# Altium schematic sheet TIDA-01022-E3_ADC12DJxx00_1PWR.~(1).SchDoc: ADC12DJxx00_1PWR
size 431 x 279 mm; Date: Not shown in title block; ApprovedBy: Not shown in title block; CheckedBy: Not shown in title block; Author: Not shown in title block; CompanyName: Not shown in title block; DrawnBy: Avinash N; Engineer: Not shown in title block; Organization: Not shown in title block; Address1: Not shown in title block; Address2: Not shown in title block; Address3: Not shown in title block; Address4: Not shown in title block; DocumentNumber: 1; Revision: Use project parameter SCH_Rev; SheetNumber: 7; SheetTotal: 26; PageSetup: Record=PageOptions¦CenterHorizontal=True¦CenterVertical=True¦PrintScale=1.00¦XCorrection=1.00¦YCorrection=1.00¦PrintKind=0¦BorderSize=5000000¦LeftOffset=0¦BottomOffset=0¦Orientation=2¦PaperLength=1000¦PaperWidth=1000¦Scale=100¦PaperSource=15¦PrintQuality=600¦MediaType=1¦DitherType=10¦PaperKind=Letter¦PrintScaleMode=1
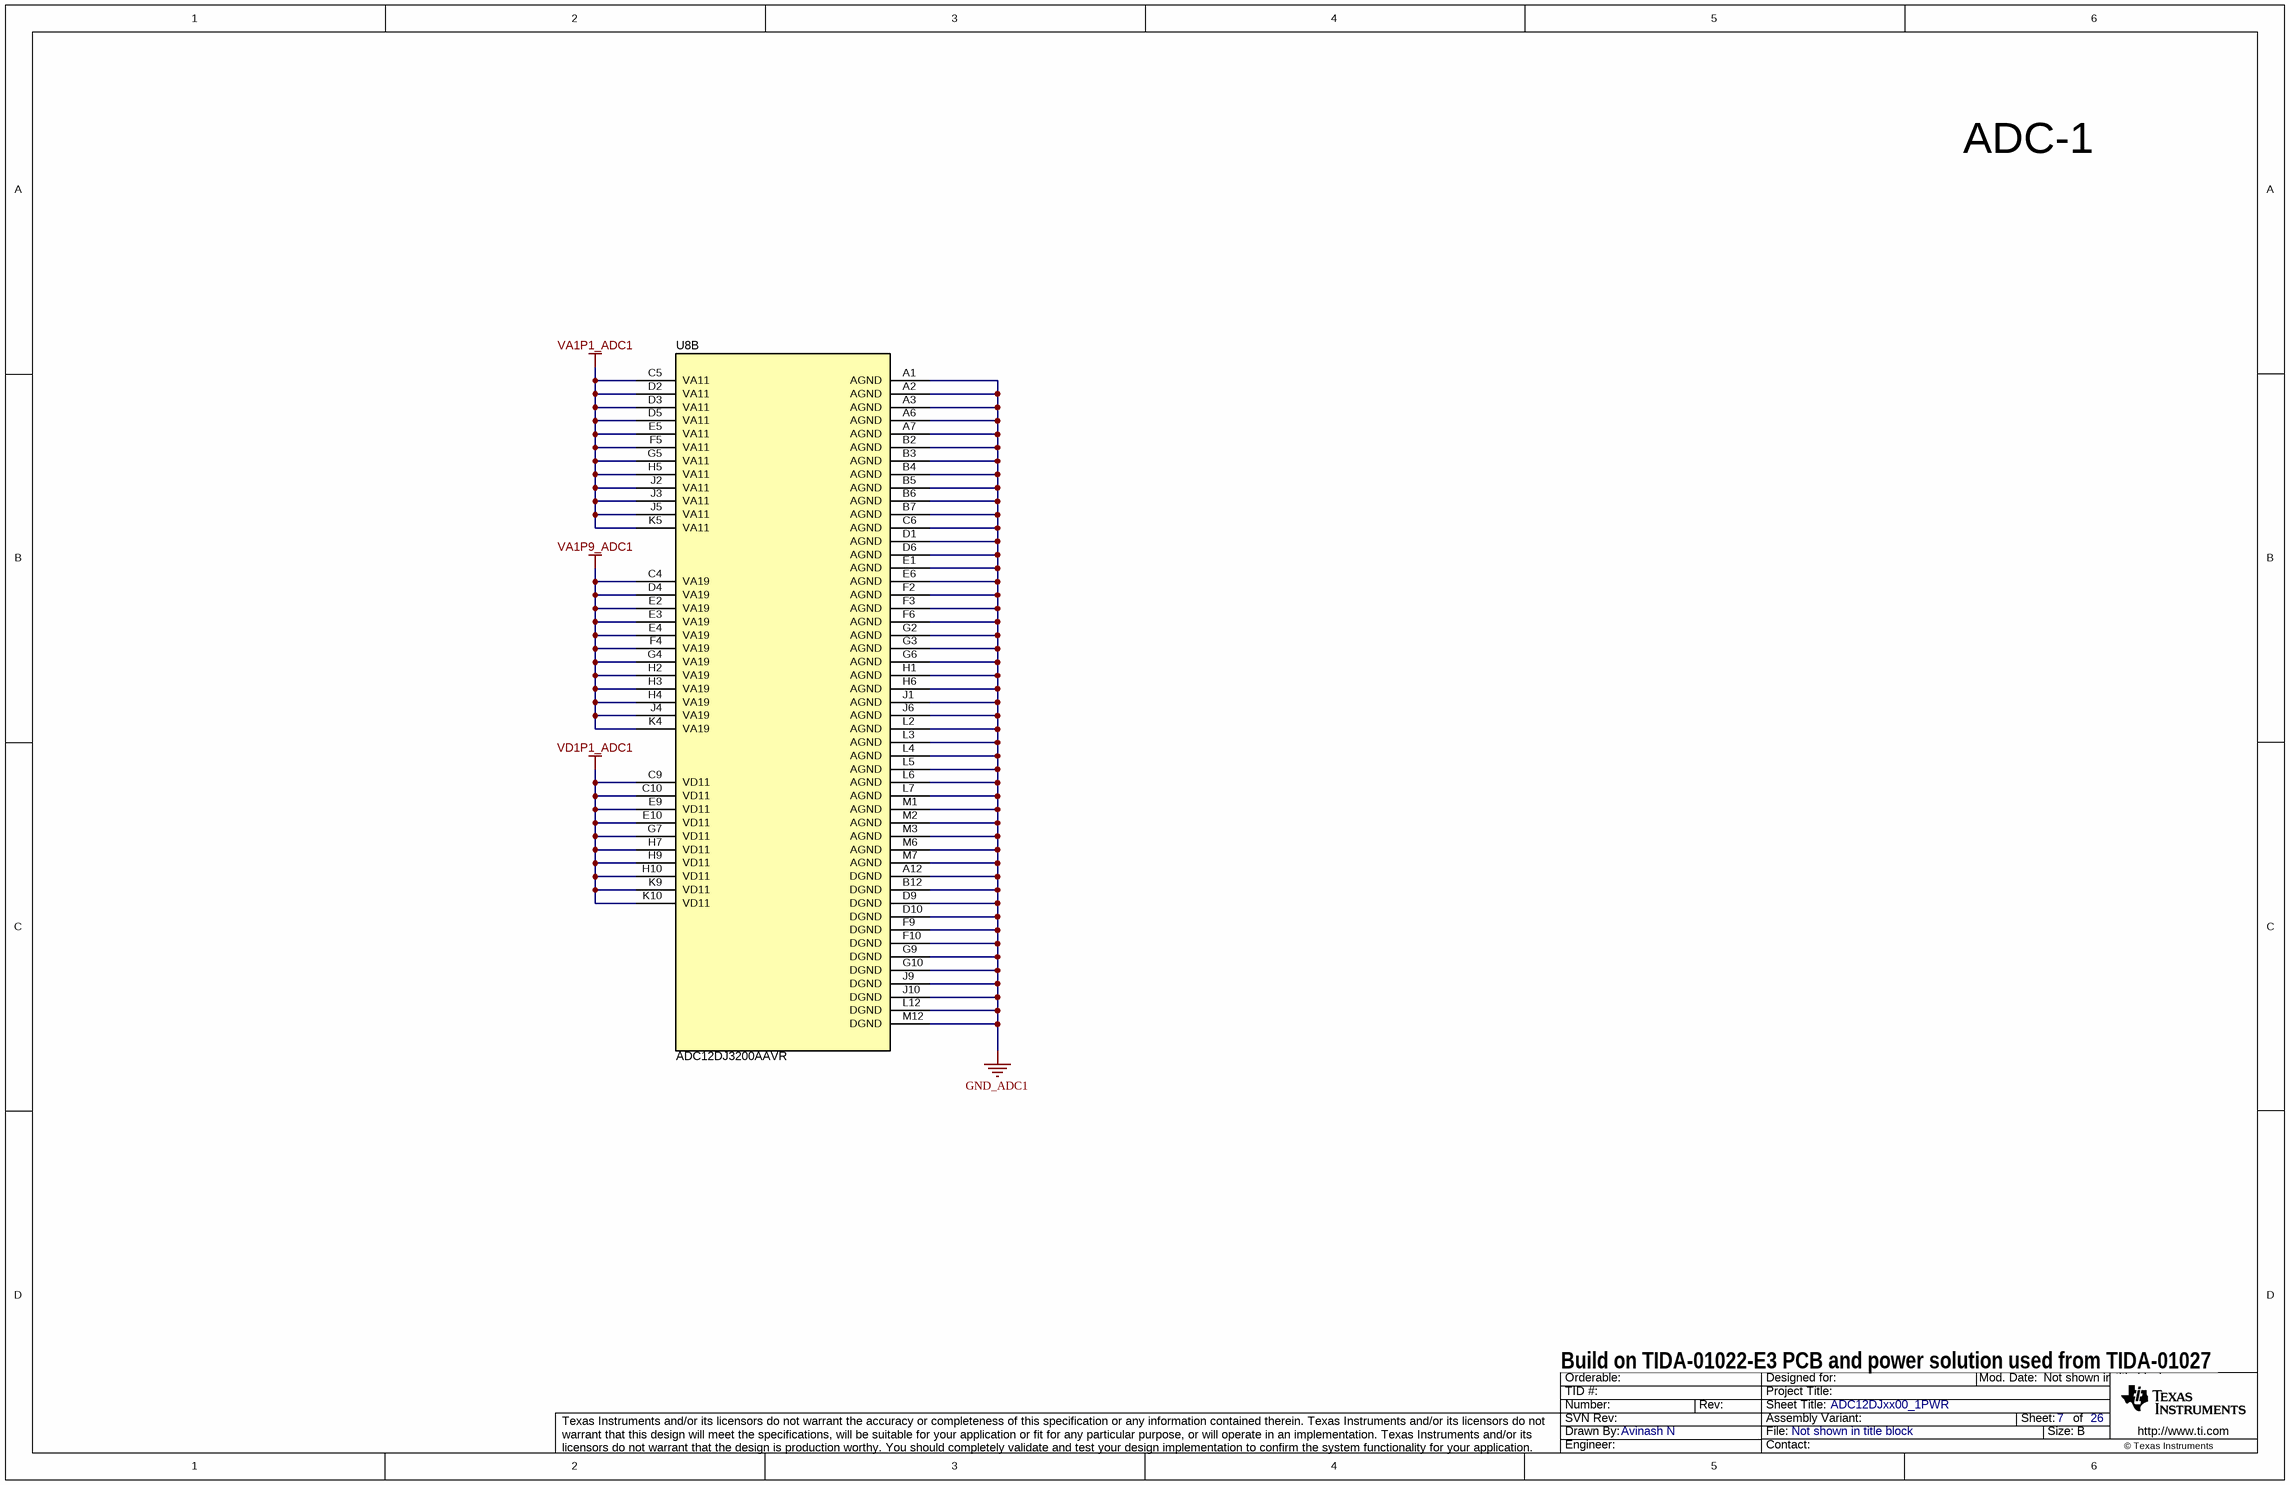
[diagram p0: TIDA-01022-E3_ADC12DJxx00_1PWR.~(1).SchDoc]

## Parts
U8  ADC12DJ3200AAVR  [AAV0144A]  (part B of 2)

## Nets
GND_ADC1: U8.A1(AGND) U8.A2(AGND) U8.A3(AGND) U8.A6(AGND) U8.A7(AGND) U8.A12(DGND) U8.B2(AGND) U8.B3(AGND) U8.B4(AGND) U8.B5(AGND) U8.B6(AGND) U8.B7(AGND) U8.B12(DGND) U8.C6(AGND) U8.D1(AGND) U8.D6(AGND) U8.D9(DGND) U8.D10(DGND) U8.E1(AGND) U8.E6(AGND) U8.F2(AGND) U8.F3(AGND) U8.F6(AGND) U8.F9(DGND) U8.F10(DGND) U8.G2(AGND) U8.G3(AGND) U8.G6(AGND) U8.G9(DGND) U8.G10(DGND) U8.H1(AGND) U8.H6(AGND) U8.J1(AGND) U8.J6(AGND) U8.J9(DGND) U8.J10(DGND) U8.L2(AGND) U8.L3(AGND) U8.L4(AGND) U8.L5(AGND) U8.L6(AGND) U8.L7(AGND) U8.L12(DGND) U8.M1(AGND) U8.M2(AGND) U8.M3(AGND) U8.M6(AGND) U8.M7(AGND) U8.M12(DGND)
VA1P1_ADC1: U8.C5(VA11) U8.D2(VA11) U8.D3(VA11) U8.D5(VA11) U8.E5(VA11) U8.F5(VA11) U8.G5(VA11) U8.H5(VA11) U8.J2(VA11) U8.J3(VA11) U8.J5(VA11) U8.K5(VA11)
VA1P9_ADC1: U8.C4(VA19) U8.D4(VA19) U8.E2(VA19) U8.E3(VA19) U8.E4(VA19) U8.F4(VA19) U8.G4(VA19) U8.H2(VA19) U8.H3(VA19) U8.H4(VA19) U8.J4(VA19) U8.K4(VA19)
VD1P1_ADC1: U8.C9(VD11) U8.C10(VD11) U8.E9(VD11) U8.E10(VD11) U8.G7(VD11) U8.H7(VD11) U8.H9(VD11) U8.H10(VD11) U8.K9(VD11) U8.K10(VD11)

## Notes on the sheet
- ADC-1
- Build on TIDA-01022-E3 PCB and power solution used from TIDA-01027

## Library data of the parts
U8 = ADC12DJ3200AAVR: 6.4-GSPS Single Channel or 3.2-GSPS Dual Channel 12-bit Analog-to-Digital Converter (ADC) Family, AAV0144A (FCBGA-144); Alternate PartNumber: ADC12DJ3200AAVT; Manufacturer: Texas Instruments; SymbolCreator: Altium; SizeArea_mm2: 100; SizeAreaWB_mm2: 144; SizeX_mm: 10; SizeZ_mm: 1.94; CompType: IC; U/M: EA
